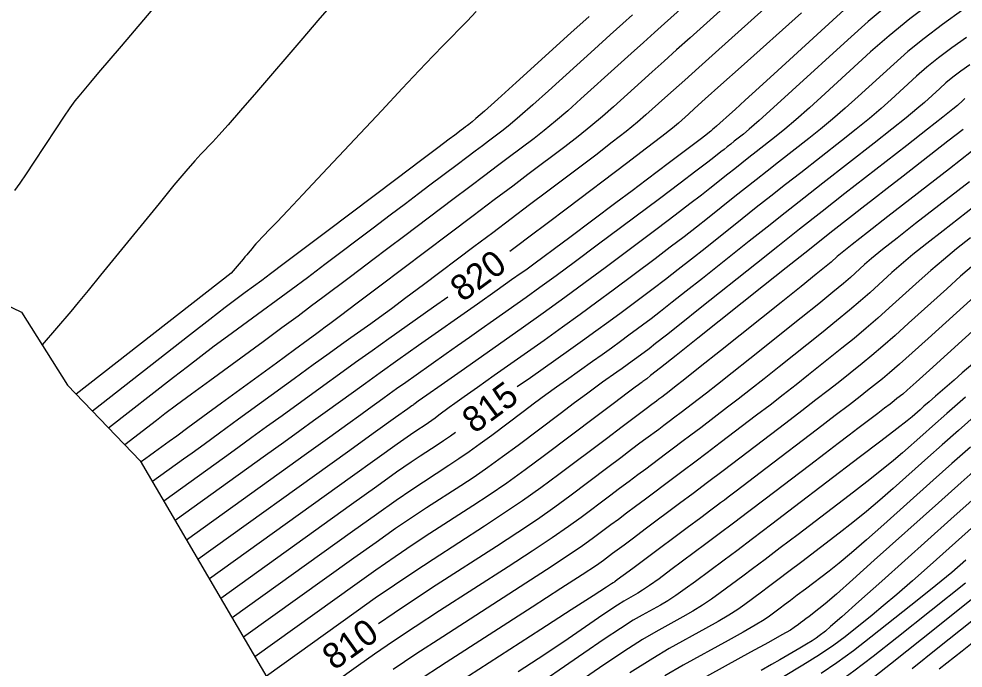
# Model space of a CAD drawing. Extents: x 2079879 to 2092887, y 778083 to 784051.
# Drawn here: x 2083804.7 to 2083907.9, y 780720.7 to 780791.7 of the extents above; entities that cross this region are included whole.
import ezdxf

# ---------------------------------------------------------------- set-up
doc = ezdxf.new("R2010")
doc.units = 0
for name, color, linetype in [('DT_X_Contour_Major', 7, 'Continuous'), ('DT_X_Contour_Minor', 7, 'Continuous'), ('DT_X_TIN_Hull', 7, 'Continuous')]:
    doc.layers.add(name, color=color, linetype=linetype)

msp = doc.modelspace()

# ---------------------------------------------------------------- linework, layer by layer
at = {"layer": 'DT_X_Contour_Major'}
for points in [[(2083867.02, 780791.98), (2083865.04, 780790.19), (2083859.04, 780784.76), (2083857.05, 780782.96), (2083855.59, 780781.65), (2083854.65, 780780.82), (2083854.25, 780780.47), (2083853.87, 780780.18), (2083853.71, 780780.06), (2083853.52, 780779.92), (2083853.3, 780779.75), (2083853.05, 780779.56), (2083852.33, 780779.03), (2083851.74, 780778.58), (2083850.49, 780777.64), (2083848.59, 780776.21), (2083846.04, 780774.28), (2083838.35, 780768.48), (2083835.74, 780766.52), (2083833.69, 780764.97), (2083832.18, 780763.85), (2083831.23, 780763.14), (2083829.42, 780761.81), (2083828.54, 780761.16), (2083827.25, 780760.17), (2083825.56, 780758.86), (2083823.46, 780757.23), (2083812.73, 780748.84)], [(2083890.24, 780792.4), (2083883.64, 780786.49), (2083881.42, 780784.51), (2083879.72, 780782.98), (2083878.54, 780781.92), (2083877.87, 780781.32), (2083876.78, 780780.34), (2083876.12, 780779.78), (2083874.96, 780778.87), (2083873.29, 780777.58), (2083871.12, 780775.93), (2083864.66, 780771.05), (2083862.42, 780769.36), (2083860.56, 780767.96), (2083859.08, 780766.84), (2083858.35, 780766.29)], [(2083908.26, 780789.7), (2083906.67, 780788.56), (2083905.23, 780787.47), (2083903.95, 780786.44), (2083902.83, 780785.46), (2083900.06, 780782.92), (2083898.94, 780781.92), (2083897.66, 780780.83), (2083896.22, 780779.66), (2083894.62, 780778.39), (2083890.15, 780774.91), (2083888.49, 780773.61), (2083886.87, 780772.34), (2083885.29, 780771.09), (2083883.75, 780769.86), (2083879.7, 780766.63), (2083878.2, 780765.45), (2083876.76, 780764.32), (2083875.36, 780763.25), (2083874.02, 780762.23), (2083870.51, 780759.6), (2083869.16, 780758.6), (2083867.75, 780757.57), (2083866.29, 780756.51), (2083864.76, 780755.42), (2083860.6, 780752.49), (2083859.17, 780751.48)], [(2083908.59, 780773.92), (2083902.7, 780769.34), (2083900.69, 780767.77), (2083899.1, 780766.51), (2083897.91, 780765.53), (2083897.13, 780764.86), (2083895.59, 780763.46), (2083894.82, 780762.79), (2083893.67, 780761.84), (2083892.13, 780760.59), (2083890.21, 780759.05), (2083884.59, 780754.56), (2083882.65, 780753.02), (2083881.07, 780751.77), (2083879.84, 780750.8), (2083878.96, 780750.13), (2083877.09, 780748.7), (2083876.41, 780748.19), (2083875.78, 780747.71), (2083875.19, 780747.26), (2083874.64, 780746.85), (2083873.24, 780745.81), (2083872.58, 780745.32), (2083871.67, 780744.63), (2083870.5, 780743.75), (2083869.08, 780742.68), (2083864.93, 780739.56), (2083863.26, 780738.34), (2083861.37, 780737.01), (2083859.24, 780735.58), (2083856.89, 780734.04), (2083850.32, 780729.81), (2083847.94, 780728.25), (2083845.7, 780726.76), (2083844.01, 780725.6)], [(2083851.59, 780761.31), (2083850.01, 780760.19), (2083845.12, 780756.74), (2083843.29, 780755.45), (2083841.5, 780754.17), (2083839.74, 780752.9), (2083838.02, 780751.65), (2083833.45, 780748.32), (2083831.77, 780747.11), (2083830.16, 780745.94), (2083828.63, 780744.83), (2083827.17, 780743.78), (2083820.52, 780739.01)], [(2083912.09, 780760.46), (2083906.2, 780755.11), (2083904.24, 780753.32), (2083902.77, 780752), (2083901.79, 780751.13), (2083901.31, 780750.71), (2083900.68, 780750.21), (2083900.37, 780749.97), (2083899.92, 780749.62), (2083899.32, 780749.16), (2083898.57, 780748.59), (2083896.39, 780746.93), (2083895.45, 780746.21), (2083894.26, 780745.3), (2083892.81, 780744.2), (2083891.12, 780742.91), (2083886.26, 780739.22), (2083884.49, 780737.87), (2083882.82, 780736.6), (2083881.25, 780735.42), (2083879.77, 780734.32), (2083875.97, 780731.48), (2083874.67, 780730.52), (2083873.63, 780729.78), (2083872.86, 780729.25), (2083872.34, 780728.93), (2083871.31, 780728.36), (2083870.82, 780728.07), (2083870.11, 780727.62), (2083869.19, 780727), (2083868.05, 780726.23), (2083864.73, 780723.95), (2083863.29, 780722.97), (2083861.47, 780721.76), (2083859.25, 780720.32)], [(2083852.41, 780746.49), (2083851.87, 780746.1), (2083851.11, 780745.58), (2083850.4, 780745.11), (2083848.55, 780743.92), (2083847.56, 780743.25), (2083845.98, 780742.15), (2083843.81, 780740.6), (2083841.04, 780738.62), (2083826.76, 780728.36)], [(2083909.99, 780743.07), (2083907.71, 780741.05), (2083905.2, 780738.8), (2083898.2, 780732.53), (2083895.85, 780730.43), (2083894.06, 780728.84), (2083892.82, 780727.77), (2083892.14, 780727.21), (2083891.08, 780726.4), (2083890.71, 780726.12), (2083890.39, 780725.88), (2083890.13, 780725.68), (2083889.92, 780725.52), (2083889.45, 780725.17), (2083889.02, 780724.9), (2083888.08, 780724.37), (2083886.63, 780723.56), (2083884.67, 780722.47), (2083878.78, 780719.23)], [(2083908.78, 780728.2), (2083907, 780726.78), (2083905.13, 780725.29), (2083899.98, 780721.19), (2083898.26, 780719.82), (2083896.98, 780718.81), (2083896.12, 780718.16), (2083895.68, 780717.85), (2083895.1, 780717.51), (2083894.62, 780717.22), (2083893.64, 780716.58), (2083892.14, 780715.61), (2083890.14, 780714.31), (2083884.11, 780710.37), (2083881.79, 780708.82), (2083879.35, 780707.13), (2083876.79, 780705.28), (2083876.03, 780704.72)]]:
    msp.add_lwpolyline(points, dxfattribs=at)
at = {"layer": 'DT_X_Contour_Minor'}
for points in [[(2083804.26, 780772.95), (2083804.81, 780773.76), (2083805.51, 780774.79), (2083806.35, 780776.05), (2083808.76, 780779.72), (2083809.6, 780780.97), (2083810.29, 780781.99), (2083810.85, 780782.76), (2083811.26, 780783.28), (2083812.55, 780784.8), (2083813.44, 780785.85), (2083815.9, 780788.74), (2083819.75, 780793.29)], [(2083838.59, 780792.98), (2083837.38, 780791.56), (2083835.71, 780789.61), (2083830.65, 780783.72), (2083828.93, 780781.72), (2083827.56, 780780.15), (2083826.54, 780779.01), (2083825.87, 780778.29), (2083824.56, 780776.94), (2083823.91, 780776.22), (2083822.93, 780775.09), (2083821.63, 780773.53), (2083820.01, 780771.55), (2083815.26, 780765.7), (2083813.61, 780763.69), (2083812.25, 780762.02), (2083811.16, 780760.71), (2083810.35, 780759.75), (2083807.22, 780756.1)], [(2083878.02, 780793.69), (2083875.26, 780791.23), (2083874.17, 780790.25), (2083872.96, 780789.16), (2083871.63, 780787.95), (2083870.17, 780786.64), (2083866.13, 780782.99), (2083864.68, 780781.69), (2083863.34, 780780.54), (2083862.11, 780779.52), (2083861, 780778.66), (2083858.18, 780776.53), (2083857.01, 780775.65), (2083855.62, 780774.59), (2083853.99, 780773.37), (2083852.14, 780771.97), (2083846.89, 780768.02), (2083845.03, 780766.63), (2083843.39, 780765.4), (2083841.98, 780764.33), (2083840.79, 780763.43), (2083837.91, 780761.26), (2083836.69, 780760.35), (2083835.2, 780759.24), (2083833.43, 780757.93), (2083831.38, 780756.43), (2083825.56, 780752.17), (2083823.56, 780750.7), (2083821.92, 780749.49), (2083820.64, 780748.53), (2083819.72, 780747.82), (2083816.28, 780745.14)], [(2083882.09, 780793.26), (2083878.06, 780789.65), (2083876.59, 780788.33), (2083875.21, 780787.1), (2083873.93, 780785.94), (2083872.74, 780784.87), (2083869.68, 780782.1), (2083868.49, 780781.06), (2083867.21, 780779.98), (2083865.84, 780778.88), (2083864.37, 780777.75), (2083860.34, 780774.7), (2083858.67, 780773.44), (2083856.66, 780771.93), (2083854.34, 780770.18), (2083851.68, 780768.18), (2083844.16, 780762.52), (2083841.67, 780760.65), (2083839.84, 780759.27), (2083838.68, 780758.39), (2083838.17, 780758.01), (2083837.69, 780757.65), (2083837.25, 780757.33), (2083836.3, 780756.62), (2083834.82, 780755.54), (2083832.83, 780754.09), (2083826.84, 780749.7), (2083824.8, 780748.2), (2083823.16, 780747.01), (2083821.94, 780746.11), (2083821.13, 780745.52), (2083819.51, 780744.34), (2083818.97, 780743.95), (2083818.58, 780743.66), (2083818.32, 780743.48), (2083818.21, 780743.4), (2083818.03, 780743.27)], [(2083886.17, 780792.83), (2083880.85, 780788.07), (2083879.01, 780786.42), (2083877.47, 780785.04), (2083876.24, 780783.93), (2083875.31, 780783.09), (2083873.23, 780781.22), (2083872.31, 780780.42), (2083871.08, 780779.42), (2083869.56, 780778.23), (2083867.75, 780776.84), (2083862.5, 780772.88), (2083860.52, 780771.38), (2083858.51, 780769.87), (2083856.48, 780768.34), (2083854.43, 780766.79), (2083848.92, 780762.65), (2083847, 780761.21), (2083845.41, 780760.02), (2083844.12, 780759.08), (2083843.15, 780758.38), (2083840.97, 780756.84), (2083839.97, 780756.13), (2083838.6, 780755.15), (2083836.87, 780753.9), (2083834.78, 780752.38), (2083828.71, 780747.96), (2083826.63, 780746.44), (2083824.93, 780745.21), (2083823.62, 780744.26), (2083822.69, 780743.59), (2083819.28, 780741.14)], [(2083895.71, 780793.45), (2083893.65, 780791.58), (2083887.65, 780786.09), (2083885.63, 780784.24), (2083884.08, 780782.83), (2083882.99, 780781.83), (2083882.36, 780781.27), (2083881.31, 780780.33), (2083880.96, 780780.01), (2083880.7, 780779.78), (2083880.52, 780779.62), (2083880.44, 780779.55), (2083880.33, 780779.45), (2083880.18, 780779.33), (2083879.78, 780779.03), (2083879.16, 780778.55), (2083878.29, 780777.9), (2083875.68, 780775.92), (2083874.59, 780775.1), (2083873.27, 780774.1), (2083871.72, 780772.94), (2083869.95, 780771.61), (2083864.92, 780767.84), (2083863.24, 780766.58), (2083861.98, 780765.64), (2083861.13, 780765.01), (2083860.7, 780764.69), (2083860.1, 780764.27), (2083859.6, 780763.92), (2083858.55, 780763.18), (2083856.96, 780762.06), (2083854.82, 780760.55), (2083848.38, 780756), (2083846.12, 780754.41), (2083844.18, 780753.03), (2083842.56, 780751.87), (2083841.25, 780750.92), (2083838.18, 780748.69), (2083836.91, 780747.77), (2083835.4, 780746.68), (2083833.65, 780745.41), (2083831.65, 780743.98), (2083821.77, 780736.88)], [(2083899.73, 780793.28), (2083897.53, 780791.45), (2083895.29, 780789.45), (2083889.22, 780783.9), (2083887.18, 780782.04), (2083885.62, 780780.62), (2083884.52, 780779.66), (2083883.9, 780779.13), (2083882.88, 780778.34), (2083882.5, 780778.04), (2083882.13, 780777.75), (2083881.77, 780777.46), (2083881.41, 780777.18), (2083880.49, 780776.44), (2083879.86, 780775.96), (2083878.69, 780775.07), (2083876.97, 780773.77), (2083874.7, 780772.07), (2083867.92, 780766.98), (2083865.52, 780765.19), (2083863.43, 780763.64), (2083861.63, 780762.34), (2083860.14, 780761.27), (2083856.56, 780758.74), (2083855.23, 780757.8), (2083853.93, 780756.88), (2083852.65, 780755.99), (2083851.41, 780755.11), (2083848.12, 780752.79), (2083846.97, 780751.98), (2083845.98, 780751.27), (2083845.15, 780750.68), (2083844.49, 780750.2), (2083842.92, 780749.06), (2083842.06, 780748.43), (2083840.64, 780747.41), (2083838.66, 780745.99), (2083836.13, 780744.17), (2083823.02, 780734.75)], [(2083904.66, 780793.66), (2083902.09, 780791.72), (2083899.81, 780789.87), (2083897.8, 780788.12), (2083892.83, 780783.57), (2083891.1, 780782), (2083889.63, 780780.69), (2083888.42, 780779.66), (2083887.48, 780778.89), (2083885.3, 780777.19), (2083884.5, 780776.56), (2083883.71, 780775.94), (2083882.94, 780775.34), (2083882.19, 780774.74), (2083880.22, 780773.17), (2083879.31, 780772.46), (2083878.05, 780771.49), (2083876.43, 780770.27), (2083874.47, 780768.79), (2083868.78, 780764.52), (2083866.6, 780762.9), (2083864.35, 780761.25), (2083862.01, 780759.56), (2083859.59, 780757.84), (2083853.02, 780753.21), (2083850.86, 780751.69), (2083849.3, 780750.59), (2083848.35, 780749.92), (2083848, 780749.67), (2083847.87, 780749.58), (2083847.82, 780749.54), (2083847.78, 780749.51), (2083847.75, 780749.49), (2083847.72, 780749.47), (2083847.66, 780749.42), (2083847.2, 780749.1), (2083845.87, 780748.14), (2083843.67, 780746.56), (2083840.61, 780744.36), (2083824.26, 780732.62)], [(2083854.66, 780792.54), (2083853.7, 780791.48), (2083851.12, 780788.86), (2083849.97, 780787.68), (2083848.46, 780786.09), (2083846.59, 780784.11), (2083844.35, 780781.72), (2083837.89, 780774.83), (2083835.73, 780772.52), (2083834.07, 780770.76), (2083832.92, 780769.54), (2083832.28, 780768.87), (2083831.26, 780767.82), (2083830.9, 780767.45), (2083830.6, 780767.13), (2083830.36, 780766.86), (2083830.17, 780766.64), (2083829.75, 780766.13), (2083829.59, 780765.92), (2083829.4, 780765.7), (2083829.2, 780765.46), (2083828.97, 780765.2), (2083827.89, 780763.93), (2083810.95, 780750.7)], [(2083871.75, 780792.16), (2083870.7, 780791.21), (2083869.32, 780789.97), (2083867.6, 780788.41), (2083862.58, 780783.87), (2083860.86, 780782.33), (2083859.46, 780781.09), (2083858.38, 780780.17), (2083857.62, 780779.56), (2083856.02, 780778.36), (2083855.36, 780777.85), (2083854.57, 780777.26), (2083853.64, 780776.56), (2083852.59, 780775.77), (2083849.61, 780773.53), (2083848.38, 780772.6), (2083846.94, 780771.52), (2083845.29, 780770.27), (2083843.41, 780768.86), (2083838.13, 780764.87), (2083836.22, 780763.43), (2083834.44, 780762.11), (2083832.81, 780760.89), (2083831.31, 780759.79), (2083827.49, 780756.99), (2083826.05, 780755.93), (2083824.58, 780754.83), (2083823.1, 780753.69), (2083821.59, 780752.53), (2083814.5, 780746.99)], [(2083907.88, 780792.7), (2083905.66, 780791.11), (2083903.66, 780789.59), (2083901.88, 780788.15), (2083900.32, 780786.79), (2083896.44, 780783.24), (2083895.02, 780781.96), (2083893.64, 780780.76), (2083892.32, 780779.66), (2083891.05, 780778.64), (2083887.73, 780776.05), (2083886.49, 780775.09), (2083885.29, 780774.14), (2083884.12, 780773.21), (2083882.97, 780772.3), (2083879.96, 780769.9), (2083878.75, 780768.95), (2083877.4, 780767.9), (2083875.9, 780766.76), (2083874.25, 780765.51), (2083869.64, 780762.06), (2083867.88, 780760.75), (2083866.03, 780759.4), (2083864.11, 780758.01), (2083862.1, 780756.58), (2083856.65, 780752.74), (2083854.81, 780751.44), (2083853.38, 780750.42), (2083852.35, 780749.68), (2083851.73, 780749.23), (2083850.61, 780748.39), (2083850.21, 780748.08), (2083849.82, 780747.81), (2083849.45, 780747.55), (2083849.1, 780747.32), (2083848.2, 780746.74), (2083847.49, 780746.25), (2083846.04, 780745.22), (2083843.85, 780743.66), (2083840.91, 780741.56), (2083825.51, 780730.49)], [(2083908.63, 780786.69), (2083907.67, 780786), (2083906.8, 780785.35), (2083906.03, 780784.72), (2083905.35, 780784.13), (2083903.67, 780782.59), (2083902.85, 780781.88), (2083901.67, 780780.9), (2083900.11, 780779.66), (2083898.19, 780778.15), (2083892.57, 780773.76), (2083890.49, 780772.13), (2083888.45, 780770.53), (2083886.47, 780768.96), (2083884.53, 780767.43), (2083879.43, 780763.36), (2083877.65, 780761.94), (2083876.11, 780760.74), (2083874.83, 780759.74), (2083873.79, 780758.95), (2083871.37, 780757.14), (2083870.44, 780756.45), (2083869.47, 780755.74), (2083868.46, 780755.01), (2083867.41, 780754.26), (2083864.54, 780752.24), (2083863.44, 780751.45), (2083862.28, 780750.61), (2083861.07, 780749.72), (2083859.81, 780748.78), (2083856.37, 780746.19), (2083855.11, 780745.25), (2083853.91, 780744.39), (2083852.78, 780743.61), (2083851.7, 780742.89), (2083848.91, 780741.09), (2083847.64, 780740.25), (2083845.92, 780739.07), (2083843.77, 780737.55), (2083841.17, 780735.69), (2083828, 780726.23)], [(2083908.1, 780783.01), (2083907.87, 780782.8), (2083907.28, 780782.26), (2083906.77, 780781.84), (2083905.68, 780780.97), (2083904.01, 780779.66), (2083901.76, 780777.9), (2083894.99, 780772.62), (2083892.49, 780770.66), (2083890.03, 780768.73), (2083887.64, 780766.84), (2083885.31, 780764.99), (2083879.17, 780760.09), (2083877.09, 780758.44), (2083875.47, 780757.15), (2083874.29, 780756.23), (2083873.57, 780755.67), (2083872.24, 780754.68), (2083871.73, 780754.3), (2083871.19, 780753.91), (2083870.64, 780753.51), (2083870.06, 780753.1), (2083868.49, 780751.99), (2083867.75, 780751.46), (2083866.74, 780750.71), (2083865.44, 780749.74), (2083863.85, 780748.55), (2083859.25, 780745.09), (2083857.57, 780743.84), (2083855.96, 780742.69), (2083854.44, 780741.63), (2083853, 780740.68), (2083849.26, 780738.27), (2083847.71, 780737.25), (2083845.87, 780735.99), (2083843.73, 780734.49), (2083841.29, 780732.76), (2083829.25, 780724.11)], [(2083907.92, 780779.63), (2083906.25, 780778.34), (2083901.34, 780774.53), (2083899.62, 780773.19), (2083898.12, 780772.02), (2083896.85, 780771.03), (2083895.81, 780770.22), (2083893.33, 780768.29), (2083892.19, 780767.39), (2083890.6, 780766.13), (2083888.56, 780764.52), (2083886.09, 780762.55), (2083878.91, 780756.82), (2083876.54, 780754.93), (2083874.82, 780753.57), (2083873.75, 780752.72), (2083873.34, 780752.39), (2083873.1, 780752.22), (2083873.01, 780752.15), (2083872.91, 780752.08), (2083872.82, 780752.01), (2083872.71, 780751.93), (2083872.43, 780751.73), (2083872.07, 780751.47), (2083871.19, 780750.81), (2083869.8, 780749.76), (2083867.9, 780748.33), (2083862.13, 780743.99), (2083860.02, 780742.42), (2083858.01, 780740.98), (2083856.1, 780739.66), (2083854.3, 780738.47), (2083849.61, 780735.45), (2083847.79, 780734.25), (2083845.81, 780732.91), (2083843.69, 780731.44), (2083841.42, 780729.82), (2083830.49, 780721.98)], [(2083908.84, 780777.22), (2083906.42, 780775.35), (2083899.68, 780770.12), (2083897.44, 780768.37), (2083895.77, 780767.06), (2083894.67, 780766.18), (2083894.13, 780765.74), (2083893.47, 780765.14), (2083892.94, 780764.69), (2083891.85, 780763.8), (2083890.2, 780762.48), (2083888, 780760.72), (2083881.37, 780755.43), (2083879.15, 780753.67), (2083877.48, 780752.34), (2083876.36, 780751.45), (2083875.78, 780751), (2083874.96, 780750.37), (2083874.66, 780750.15), (2083874.38, 780749.94), (2083874.12, 780749.74), (2083873.88, 780749.56), (2083873.27, 780749.1), (2083872.82, 780748.77), (2083871.95, 780748.11), (2083870.64, 780747.13), (2083868.91, 780745.82), (2083863.71, 780741.91), (2083861.74, 780740.46), (2083859.73, 780739.03), (2083857.68, 780737.63), (2083855.6, 780736.25), (2083849.97, 780732.63), (2083847.86, 780731.25), (2083845.75, 780729.83), (2083843.65, 780728.38), (2083841.55, 780726.89), (2083831.74, 780719.85)], [(2083910.76, 780772.48), (2083905.71, 780768.56), (2083903.94, 780767.17), (2083902.42, 780765.95), (2083901.15, 780764.88), (2083900.12, 780763.98), (2083897.71, 780761.79), (2083896.7, 780760.9), (2083895.49, 780759.87), (2083894.07, 780758.7), (2083892.43, 780757.38), (2083887.8, 780753.69), (2083886.15, 780752.38), (2083884.65, 780751.2), (2083883.32, 780750.16), (2083882.14, 780749.26), (2083879.22, 780747.03), (2083878.16, 780746.23), (2083877.17, 780745.48), (2083876.25, 780744.78), (2083875.39, 780744.14), (2083873.21, 780742.51), (2083872.34, 780741.87), (2083871.39, 780741.16), (2083870.36, 780740.38), (2083869.24, 780739.54), (2083866.15, 780737.21), (2083864.78, 780736.22), (2083863, 780734.99), (2083860.8, 780733.53), (2083858.19, 780731.83), (2083850.68, 780726.99), (2083848.01, 780725.25), (2083845.64, 780723.68), (2083843.57, 780722.27), (2083841.8, 780721.02), (2083834.23, 780715.59)], [(2083908.72, 780767.79), (2083907.19, 780766.58), (2083905.75, 780765.39), (2083904.39, 780764.23), (2083903.11, 780763.1), (2083899.83, 780760.12), (2083898.59, 780759.01), (2083897.31, 780757.9), (2083896, 780756.8), (2083894.65, 780755.71), (2083891.02, 780752.82), (2083889.65, 780751.73), (2083888.24, 780750.63), (2083886.8, 780749.51), (2083885.33, 780748.39), (2083881.36, 780745.36), (2083879.92, 780744.27), (2083878.57, 780743.25), (2083877.31, 780742.3), (2083876.15, 780741.43), (2083873.18, 780739.22), (2083872.1, 780738.42), (2083871.12, 780737.68), (2083870.22, 780737.01), (2083869.41, 780736.4), (2083867.37, 780734.86), (2083866.3, 780734.1), (2083864.63, 780732.97), (2083862.36, 780731.48), (2083859.49, 780729.62), (2083851.03, 780724.16), (2083848.09, 780722.25), (2083845.59, 780720.6)], [(2083909.07, 780764.83), (2083907.62, 780763.58), (2083906.11, 780762.22), (2083901.95, 780758.45), (2083900.47, 780757.11), (2083899.13, 780755.93), (2083897.93, 780754.91), (2083896.87, 780754.05), (2083894.24, 780751.95), (2083893.14, 780751.08), (2083891.82, 780750.06), (2083890.28, 780748.87), (2083888.51, 780747.51), (2083883.49, 780743.69), (2083881.67, 780742.31), (2083879.96, 780741.02), (2083878.38, 780739.83), (2083876.91, 780738.73), (2083873.15, 780735.92), (2083871.86, 780734.96), (2083870.84, 780734.2), (2083870.08, 780733.63), (2083869.58, 780733.26), (2083868.59, 780732.51), (2083867.82, 780731.98), (2083866.27, 780730.95), (2083863.92, 780729.43), (2083860.79, 780727.4), (2083851.39, 780721.34), (2083848.16, 780719.25)], [(2083909.1, 780761.34), (2083904.08, 780756.78), (2083902.35, 780755.22), (2083900.95, 780753.97), (2083899.86, 780753.02), (2083899.09, 780752.38), (2083897.46, 780751.08), (2083896.66, 780750.45), (2083895.49, 780749.54), (2083893.93, 780748.35), (2083892, 780746.88), (2083886.35, 780742.58), (2083884.48, 780741.15), (2083883.1, 780740.1), (2083882.21, 780739.42), (2083881.81, 780739.12), (2083881.4, 780738.81), (2083881.05, 780738.55), (2083880.33, 780738.01), (2083879.23, 780737.18), (2083877.74, 780736.07), (2083873.27, 780732.74), (2083871.8, 780731.65), (2083870.74, 780730.86), (2083870.1, 780730.38), (2083869.88, 780730.22), (2083869.82, 780730.19), (2083869.8, 780730.17), (2083869.76, 780730.15), (2083869.71, 780730.12), (2083869.65, 780730.07), (2083869.47, 780729.95), (2083868.94, 780729.61), (2083867.47, 780728.66), (2083865.07, 780727.11), (2083861.73, 780724.96), (2083851.59, 780718.42)], [(2083908.96, 780754.03), (2083907.82, 780753.02), (2083906.93, 780752.24), (2083904.89, 780750.47), (2083904.19, 780749.86), (2083903.63, 780749.37), (2083903.2, 780749), (2083902.91, 780748.74), (2083902.32, 780748.21), (2083901.79, 780747.78), (2083900.65, 780746.89), (2083898.91, 780745.55), (2083896.56, 780743.76), (2083889.47, 780738.36), (2083887, 780736.48), (2083884.89, 780734.89), (2083883.16, 780733.58), (2083881.8, 780732.56), (2083878.66, 780730.22), (2083877.54, 780729.4), (2083876.52, 780728.7), (2083875.61, 780728.11), (2083874.81, 780727.64), (2083872.81, 780726.54), (2083871.85, 780725.97), (2083870.47, 780725.08), (2083868.67, 780723.89), (2083866.45, 780722.38), (2083859.99, 780717.94)], [(2083908.17, 780750.36), (2083906.12, 780748.57), (2083904.56, 780747.2), (2083903.49, 780746.26), (2083901.29, 780744.29), (2083900.3, 780743.44), (2083899, 780742.38), (2083897.39, 780741.11), (2083895.45, 780739.62), (2083889.87, 780735.37), (2083887.92, 780733.89), (2083886.27, 780732.63), (2083884.9, 780731.6), (2083883.83, 780730.8), (2083881.36, 780728.96), (2083880.41, 780728.27), (2083879.41, 780727.61), (2083878.37, 780726.97), (2083877.28, 780726.35), (2083874.3, 780724.71), (2083872.87, 780723.86), (2083870.82, 780722.55), (2083868.15, 780720.77), (2083864.86, 780718.53)], [(2083909.46, 780748.54), (2083907.41, 780746.74), (2083905.61, 780745.15), (2083904.06, 780743.77), (2083900.26, 780740.37), (2083898.82, 780739.1), (2083897.36, 780737.87), (2083895.87, 780736.66), (2083894.35, 780735.48), (2083890.27, 780732.38), (2083888.85, 780731.3), (2083887.64, 780730.38), (2083886.65, 780729.63), (2083885.86, 780729.04), (2083884.06, 780727.69), (2083883.28, 780727.15), (2083882.3, 780726.53), (2083881.12, 780725.83), (2083879.74, 780725.06), (2083875.79, 780722.88), (2083873.97, 780721.81), (2083871.46, 780720.21)], [(2083908.7, 780744.91), (2083906.66, 780743.1), (2083904.63, 780741.29), (2083899.23, 780736.45), (2083897.33, 780734.77), (2083895.71, 780733.36), (2083894.34, 780732.22), (2083893.25, 780731.35), (2083890.68, 780729.39), (2083889.78, 780728.71), (2083889.02, 780728.13), (2083888.39, 780727.65), (2083887.89, 780727.28), (2083886.75, 780726.43), (2083886.15, 780726.03), (2083885.19, 780725.45), (2083883.88, 780724.69), (2083882.21, 780723.77), (2083877.29, 780721.06), (2083875.29, 780719.91)], [(2083909.21, 780739.39), (2083906.56, 780737.03), (2083899.01, 780730.26), (2083896.5, 780728.01), (2083894.64, 780726.35), (2083893.42, 780725.28), (2083892.85, 780724.79), (2083892.18, 780724.26), (2083891.86, 780724.02), (2083891.4, 780723.72), (2083890.8, 780723.35), (2083890.06, 780722.91), (2083887.88, 780721.65), (2083886.96, 780721.12), (2083885.83, 780720.47)], [(2083909.85, 780736.97), (2083904.31, 780732.01), (2083902.36, 780730.28), (2083900.65, 780728.78), (2083899.18, 780727.54), (2083897.95, 780726.53), (2083895, 780724.18), (2083893.76, 780723.25), (2083892.22, 780722.21), (2083890.4, 780721.06), (2083888.29, 780719.8)], [(2083908.22, 780732.54), (2083906.66, 780731.21), (2083904.94, 780729.79), (2083903.06, 780728.28), (2083897.83, 780724.11), (2083895.91, 780722.63), (2083894.1, 780721.31), (2083892.38, 780720.15)], [(2083908.16, 780730.03), (2083900.65, 780724.04), (2083898.07, 780722.01), (2083895.97, 780720.41), (2083894.36, 780719.24), (2083893.22, 780718.5), (2083890.83, 780717.11), (2083889.84, 780716.52), (2083888.69, 780715.81), (2083887.35, 780714.96), (2083885.85, 780713.98), (2083881.6, 780711.21), (2083879.96, 780710.12), (2083878.24, 780708.92), (2083876.43, 780707.62), (2083874.54, 780706.22), (2083869.37, 780702.33), (2083867.45, 780700.9), (2083865.54, 780699.5), (2083863.66, 780698.15), (2083861.8, 780696.84), (2083853.16, 780690.83)], [(2083913.63, 780729.65), (2083905.15, 780722.91), (2083902.34, 780720.67)], [(2083915.29, 780728.56), (2083907.81, 780722.61), (2083905.28, 780720.61)]]:
    msp.add_lwpolyline(points, dxfattribs=at)
at = {"layer": 'DT_X_TIN_Hull'}
msp.add_lwpolyline([(2083782.89, 780770.26), (2083804.98, 780759.65), (2083810.01, 780751.68), (2083817.96, 780743.39), (2083842.66, 780701.2), (2083856.68, 780687.35), (2083869, 780676.57), (2083846.43, 780635.19)], dxfattribs=at)

# ---------------------------------------------------------------- texts
at = {"layer": 'DT_X_Contour_Major'}
for s, rotation, p in [('820', 36.3941, (2083853.18, 780760.7)), ('815', 36.4185, (2083854.48, 780746.31)), ('810', 35.4885, (2083839.15, 780720.43))]:
    msp.add_text(s, height=2.8, rotation=rotation, dxfattribs=at).set_placement(p)

doc.saveas('drawing.dxf')
